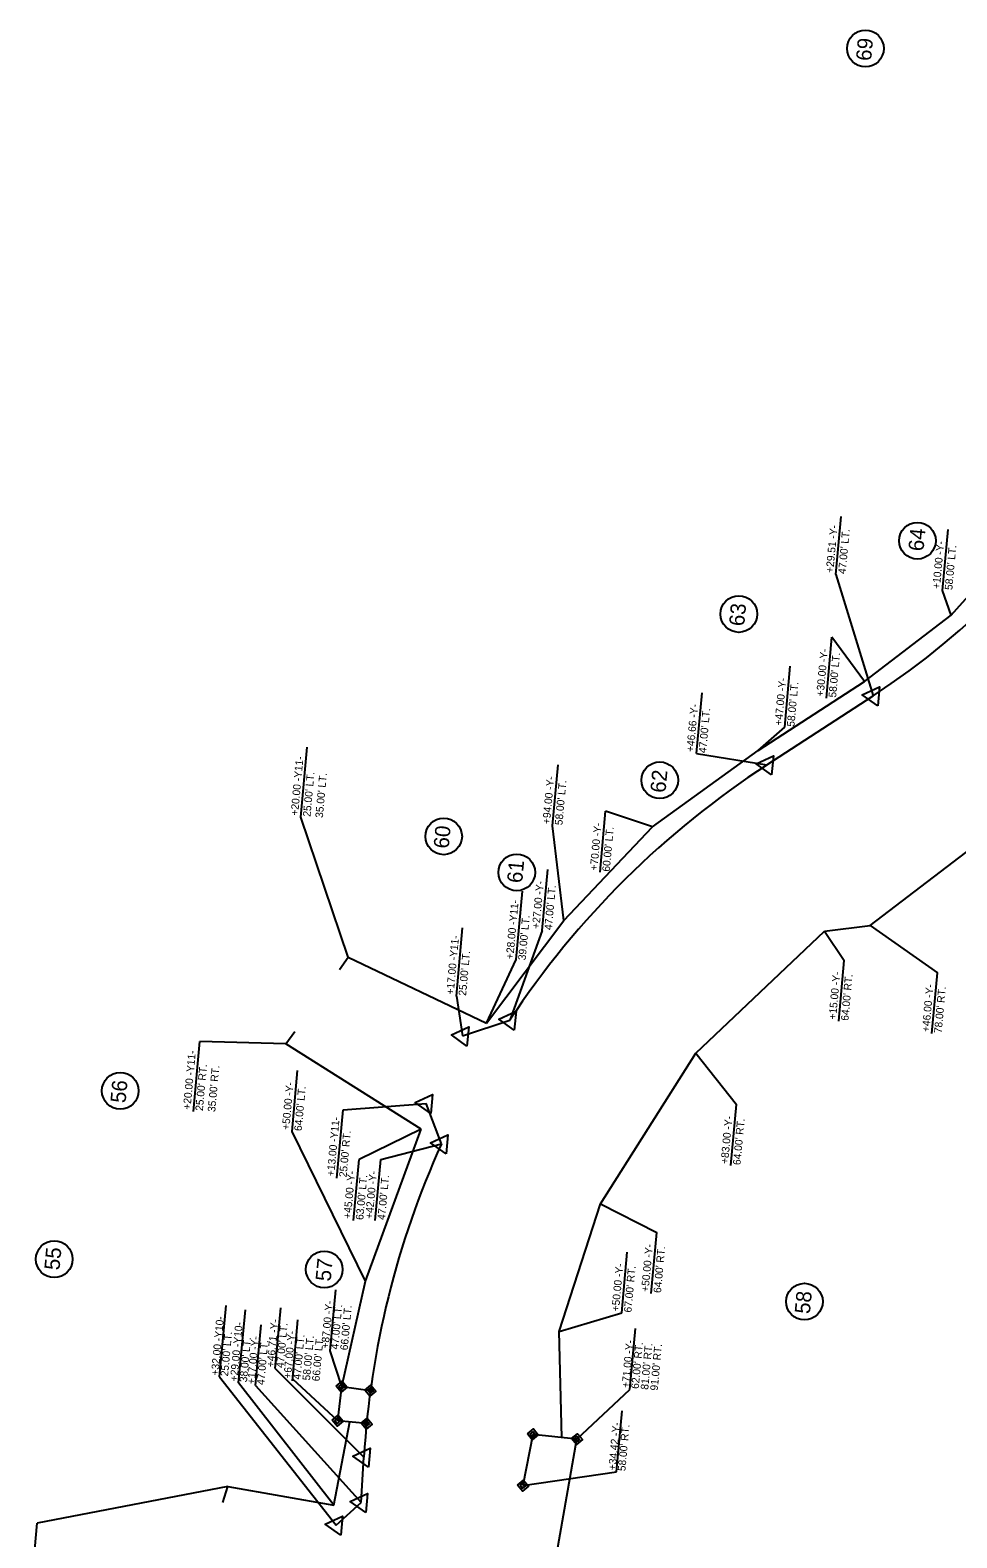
# Model space of a CAD drawing. Extents: x 2010883 to 2014849, y 442000 to 447413.
# Drawn here: x 2011804 to 2012411, y 445432 to 446419 of the extents above; entities that cross this region are included whole.
import ezdxf

# ---------------------------------------------------------------- set-up
doc = ezdxf.new("R2010")
doc.units = 0
for name, color, linetype in [('Prop Easement Construction', 7, 'Continuous'), ('Prop Easement Construction Station Offsets', 7, 'Continuous'), ('Prop Easement Permanent Drainage', 7, 'Continuous'), ('Prop Easement Permanent Utility', 7, 'Continuous'), ('Prop Easement Permanent Utility Station Offsets', 7, 'Continuous'), ('Prop Parcel Number CELL', 7, 'Continuous'), ('Prop Parcel Number Text', 7, 'Continuous'), ('Prop ROW Marker CELL', 7, 'Continuous'), ('Prop ROW Permanent Easement CELL', 7, 'Continuous'), ('Prop ROW RW Lines', 7, 'Continuous'), ('Prop ROW Station Offsets', 7, 'Continuous')]:
    doc.layers.add(name, color=color, linetype=linetype)

msp = doc.modelspace()

# ---------------------------------------------------------------- linework, layer by layer
at = {"layer": 'Prop Easement Construction'}
for p, q in [((2012407.17, 446035.72), (2012483.95, 446122.35)), ((2012350.43, 445992.48), (2012407.17, 446035.72)), ((2012280.87, 445947.29), (2012350.43, 445992.48)), ((2012211.57, 445897.38), (2012280.87, 445947.29)), ((2012153.67, 445836.06), (2012211.57, 445897.38)), ((2012354.2, 445832.75), (2012445.39, 445902.48)), ((2012102.87, 445768.83), (2012153.67, 445836.06)), ((2012240.02, 445749.18), (2012324.14, 445828.93)), ((2012324.14, 445828.93), (2012354.2, 445832.75)), ((2012006.62, 445803.98), (2012012.44, 445812.11)), ((2012012.44, 445812.11), (2012102.87, 445768.83)), ((2011971.66, 445755.22), (2011977.49, 445763.35)), ((2012060.29, 445699.56), (2011971.66, 445755.22)), ((2012177.54, 445650.51), (2012240.02, 445749.18)), ((2012023.75, 445599.9), (2012060.29, 445699.56)), ((2012150.57, 445567.08), (2012177.54, 445650.51)), ((2012008.16, 445531), (2012023.75, 445599.9)), ((2012152.18, 445497.67), (2012150.57, 445567.08)), ((2012002.92, 445453.48), (2012013.5, 445507.91)), ((2011930.27, 445455.17), (2011933.71, 445465.62)), ((2011933.71, 445465.62), (2012002.92, 445453.48))]:
    msp.add_line(p, q, dxfattribs=at)
at = {"layer": 'Prop Easement Construction Station Offsets'}
for p, q in [((2012401.51, 446051.91), (2012405.17, 446091.75)), ((2012407.17, 446035.72), (2012401.51, 446051.91)), ((2012325.42, 445981.55), (2012329.08, 446021.38)), ((2012350.43, 445992.48), (2012329.08, 446021.38)), ((2012298.15, 445962.5), (2012301.81, 446002.33)), ((2012280.87, 445947.29), (2012298.15, 445962.5)), ((2011981.37, 445903.57), (2011985.58, 445949.38)), ((2012146.25, 445898.02), (2012149.92, 445937.85)), ((2012177.27, 445867.64), (2012180.93, 445907.48)), ((2012211.57, 445897.38), (2012180.93, 445907.48)), ((2012012.44, 445812.11), (2011981.37, 445903.57)), ((2012153.67, 445836.06), (2012146.25, 445898.02)), ((2012122.31, 445810.4), (2012126.43, 445855.21)), ((2012324.14, 445828.93), (2012337.19, 445809.92)), ((2012354.2, 445832.75), (2012398.23, 445801.79)), ((2012102.87, 445768.83), (2012122.31, 445810.4)), ((2012333.53, 445770.09), (2012337.19, 445809.92)), ((2012394.57, 445761.96), (2012398.23, 445801.79)), ((2011911.07, 445710.93), (2011915.28, 445756.74)), ((2011971.66, 445755.22), (2011915.28, 445756.74)), ((2012240.02, 445749.18), (2012266.53, 445715.49)), ((2011975.63, 445697.91), (2011979.29, 445737.74)), ((2012262.86, 445675.66), (2012266.53, 445715.49)), ((2012023.75, 445599.9), (2011975.63, 445697.91)), ((2012060.29, 445699.56), (2012019.59, 445679.57)), ((2012015.93, 445639.74), (2012019.59, 445679.57)), ((2012177.54, 445650.51), (2012214.48, 445631.77)), ((2012210.82, 445591.94), (2012214.48, 445631.77)), ((2012191.48, 445579.18), (2012195.14, 445619.01)), ((2012000.57, 445554.51), (2012004.23, 445594.35)), ((2011940.7, 445533.45), (2011945.09, 445581.25)), ((2012150.57, 445567.08), (2012191.48, 445579.18)), ((2011975.89, 445534.77), (2011979.55, 445574.6)), ((2012008.16, 445531), (2012000.57, 445554.51)), ((2012002.92, 445453.48), (2011940.7, 445533.45)), ((2012005.54, 445508.69), (2011976.19, 445535.9)), ((2011933.71, 445465.62), (2011808.88, 445441.67)), ((2011804.21, 445390.84), (2011808.88, 445441.67))]:
    msp.add_line(p, q, dxfattribs=at)
at = {"layer": 'Prop Easement Permanent Drainage'}
for p, q in [((2012005.54, 445508.69), (2012008.16, 445531)), ((2012008.16, 445531), (2012026.98, 445528.44)), ((2012005.65, 445509.81), (2012005.65, 445509.81)), ((2012005.65, 445509.81), (2012005.65, 445509.81)), ((2012024.45, 445506.83), (2012005.54, 445508.69))]:
    msp.add_line(p, q, dxfattribs=at)
at = {"layer": 'Prop Easement Permanent Utility'}
for p, q in [((2012119.36, 445252.89), (2012162.12, 445496.62)), ((2012133.28, 445499.67), (2012126.77, 445466.24)), ((2012162.12, 445496.62), (2012133.28, 445499.67))]:
    msp.add_line(p, q, dxfattribs=at)
at = {"layer": 'Prop Easement Permanent Utility Station Offsets'}
for p, q in [((2012196.86, 445529.16), (2012200.52, 445568.99)), ((2012162.12, 445496.62), (2012196.86, 445529.16)), ((2012188.1, 445475.3), (2012191.76, 445515.13)), ((2012126.77, 445466.24), (2012188.1, 445475.3))]:
    msp.add_line(p, q, dxfattribs=at)
at = {"layer": 'Prop Parcel Number CELL'}
for p, q in [((2012351.01, 446406.59), (2012351.01, 446406.59)), ((2012385.03, 446084.49), (2012385.03, 446084.49)), ((2012268.15, 446036.54), (2012268.15, 446036.54)), ((2012216.35, 445927.76), (2012216.35, 445927.76)), ((2012074.93, 445891.05), (2012074.93, 445891.05)), ((2012122.77, 445867.45), (2012122.77, 445867.45)), ((2011863.21, 445724.55), (2011863.21, 445724.55)), ((2011819.99, 445614.37), (2011819.99, 445614.37)), ((2011996.75, 445607.67), (2011996.75, 445607.67)), ((2012311.04, 445586.6), (2012311.04, 445586.6))]:
    msp.add_line(p, q, dxfattribs=at)
for centre in [(2012351.01, 446406.59), (2012385.03, 446084.49), (2012268.15, 446036.54), (2012216.35, 445927.76), (2012074.93, 445891.05), (2012122.77, 445867.45), (2011863.21, 445724.55), (2011819.99, 445614.37), (2011996.75, 445607.67), (2012311.04, 445586.6)]:
    msp.add_circle(centre, 12, dxfattribs=at)
at = {"layer": 'Prop ROW Marker CELL'}
for p, q in [((2012356.05, 445983.01), (2012356.05, 445983.01)), ((2012286.57, 445937.88), (2012286.57, 445937.88)), ((2012118.13, 445770.76), (2012118.13, 445770.76)), ((2012087.17, 445760.42), (2012087.17, 445760.42)), ((2012063.42, 445716.24), (2012063.42, 445716.24)), ((2012073.47, 445689.9), (2012073.47, 445689.9)), ((2012008.16, 445531), (2012008.16, 445531)), ((2012026.98, 445528.44), (2012026.98, 445528.44)), ((2012005.54, 445508.69), (2012005.54, 445508.69)), ((2012024.45, 445506.83), (2012024.45, 445506.83)), ((2012133.28, 445499.67), (2012133.28, 445499.67)), ((2012162.12, 445496.62), (2012162.12, 445496.62)), ((2012022.7, 445484.83), (2012022.7, 445484.83)), ((2012126.77, 445466.24), (2012126.77, 445466.24)), ((2012020.92, 445455.17), (2012020.92, 445455.17)), ((2012004.58, 445440.31), (2012004.58, 445440.31))]:
    msp.add_line(p, q, dxfattribs=at)
for points in [[(2012359.06, 445976.46), (2012348.88, 445983.67), (2012360.21, 445988.91)], [(2012289.59, 445931.32), (2012279.4, 445938.54), (2012290.73, 445943.77)], [(2012121.14, 445764.21), (2012110.96, 445771.42), (2012122.29, 445776.66)], [(2012090.18, 445753.87), (2012080, 445761.08), (2012091.33, 445766.32)], [(2012066.43, 445709.69), (2012056.25, 445716.9), (2012067.58, 445722.14)], [(2012076.48, 445683.35), (2012066.3, 445690.56), (2012077.63, 445695.8)], [(2012025.71, 445478.27), (2012015.53, 445485.49), (2012026.86, 445490.72)], [(2012023.93, 445448.62), (2012013.75, 445455.83), (2012025.07, 445461.06)], [(2012007.59, 445433.75), (2011997.41, 445440.97), (2012008.74, 445446.2)]]:
    msp.add_lwpolyline(points, close=True, dxfattribs=at)
at = {"layer": 'Prop ROW Permanent Easement CELL'}
for points in [[(2012004.57, 445531.33), (2012008.49, 445534.59), (2012011.74, 445530.67), (2012007.83, 445527.42)], [(2012006.36, 445531.17), (2012008.32, 445532.8), (2012009.95, 445530.84), (2012007.99, 445529.21)], [(2012023.4, 445528.77), (2012027.31, 445532.02), (2012030.57, 445528.11), (2012026.65, 445524.85)], [(2012025.19, 445528.6), (2012027.15, 445530.23), (2012028.77, 445528.27), (2012026.82, 445526.64)], [(2012001.95, 445509.02), (2012005.87, 445512.27), (2012009.12, 445508.36), (2012005.21, 445505.1)], [(2012003.75, 445508.85), (2012005.7, 445510.48), (2012007.33, 445508.52), (2012005.37, 445506.9)], [(2012020.86, 445507.16), (2012024.78, 445510.41), (2012028.03, 445506.5), (2012024.12, 445503.24)], [(2012022.65, 445506.99), (2012024.61, 445508.62), (2012026.24, 445506.66), (2012024.28, 445505.04)], [(2012129.7, 445500), (2012133.61, 445503.26), (2012136.87, 445499.34), (2012132.95, 445496.09)], [(2012131.49, 445499.84), (2012133.45, 445501.46), (2012135.07, 445499.51), (2012133.12, 445497.88)], [(2012158.54, 445496.95), (2012162.45, 445500.2), (2012165.7, 445496.29), (2012161.79, 445493.03)], [(2012160.33, 445496.78), (2012162.29, 445498.41), (2012163.91, 445496.45), (2012161.96, 445494.82)], [(2012123.19, 445466.57), (2012127.1, 445469.83), (2012130.36, 445465.91), (2012126.44, 445462.66)], [(2012124.98, 445466.41), (2012126.94, 445468.04), (2012128.56, 445466.08), (2012126.61, 445464.45)]]:
    msp.add_lwpolyline(points, close=True, dxfattribs=at)
at = {"layer": 'Prop ROW RW Lines'}
for p, q in [((2012286.57, 445937.88), (2012356.05, 445983.01)), ((2012087.17, 445760.42), (2012118.13, 445770.76)), ((2012073.47, 445689.9), (2012063.42, 445716.24)), ((2012020.92, 445455.17), (2012022.7, 445484.82)), ((2012004.58, 445440.31), (2012020.92, 445455.17))]:
    msp.add_line(p, q, dxfattribs=at)
for centre, radius, start, end in [((2012087.46, 446396.43), 493, 303.01114, 355.42659), ((2012603.65, 445449.83), 582, 123.01114, 146.53516), ((2012603.65, 445449.83), 582, 155.63823, 176.55328)]:
    msp.add_arc(centre, radius, start, end, dxfattribs=at)
at = {"layer": 'Prop ROW Station Offsets'}
for p, q in [((2012331.7, 446062.42), (2012335.18, 446100.26)), ((2012331.7, 446062.42), (2012356.05, 445983.01)), ((2012240.4, 445945.21), (2012244.06, 445985.04)), ((2012240.4, 445945.21), (2012286.57, 445937.88)), ((2012139.37, 445829.44), (2012143.04, 445869.27)), ((2012083.22, 445786.43), (2012087.34, 445831.24)), ((2012139.37, 445829.44), (2012118.13, 445770.76)), ((2012083.22, 445786.43), (2012087.17, 445760.42)), ((2012005.01, 445667.32), (2012009.13, 445712.13)), ((2012009.13, 445712.13), (2012063.42, 445716.24)), ((2012033.85, 445679.55), (2012073.47, 445689.9)), ((2012030.18, 445639.72), (2012033.85, 445679.55)), ((2011928.19, 445537.31), (2011932.49, 445584.11)), ((2011964.62, 445542.81), (2011968.28, 445582.64)), ((2011951.83, 445531.67), (2011955.49, 445571.5)), ((2011964.62, 445542.81), (2012022.7, 445484.82)), ((2011928.19, 445537.31), (2012004.58, 445440.31)), ((2011951.83, 445531.67), (2012020.92, 445455.17))]:
    msp.add_line(p, q, dxfattribs=at)

# ---------------------------------------------------------------- texts
at = {"layer": 'Prop Easement Construction Station Offsets'}
for s, p in [('+10.00 -Y-', (2012399.75, 446052.8)), ("58.00' LT.", (2012407.84, 446052.06)), ('+30.00 -Y-', (2012323.66, 445982.44)), ("58.00' LT.", (2012331.76, 445981.7)), ('+47.00 -Y-', (2012296.39, 445963.39)), ("58.00' LT.", (2012304.48, 445962.64)), ('+20.00 -Y11-', (2011979.61, 445904.46)), ("25.00' LT.", (2011987.7, 445903.72)), ("35.00' LT.", (2011995.8, 445902.97)), ('+94.00 -Y-', (2012144.5, 445898.91)), ("58.00' LT.", (2012152.59, 445898.17)), ('+70.00 -Y-', (2012175.51, 445868.53)), ("60.00' LT.", (2012183.6, 445867.79)), ('+28.00 -Y11-', (2012120.48, 445810.54)), ("39.00' LT.", (2012128.57, 445809.8)), ('+15.00 -Y-', (2012331.77, 445770.98)), ("64.00' RT.", (2012339.86, 445770.23)), ('+46.00 -Y-', (2012392.81, 445762.85)), ("78.00' RT.", (2012400.9, 445762.11)), ('+20.00 -Y11-', (2011909.16, 445712.01)), ("25.00' RT.", (2011917.25, 445711.27)), ("35.00' RT.", (2011925.34, 445710.52)), ('+50.00 -Y-', (2011973.87, 445698.8)), ("64.00' LT.", (2011981.96, 445698.05)), ('+83.00 -Y-', (2012261.11, 445676.55)), ("64.00' RT.", (2012269.2, 445675.81)), ('+45.00 -Y-', (2012014.17, 445640.63)), ("63.00' LT.", (2012022.26, 445639.89)), ('+50.00 -Y-', (2012209.07, 445592.83)), ("64.00' RT.", (2012217.16, 445592.09)), ('+50.00 -Y-', (2012189.72, 445580.06)), ("67.00' RT.", (2012197.81, 445579.32)), ('+87.00 -Y-', (2011999.62, 445555.76)), ("47.00' LT.", (2012005.85, 445555.18)), ("66.00' LT.", (2012012.07, 445554.61)), ('+29.00 -Y10-', (2011939.91, 445534.25)), ("38.00' LT.", (2011946.13, 445533.68)), ('+67.00 -Y-', (2011974.94, 445536.01)), ("47.00' LT.", (2011981.17, 445535.44)), ("58.00' LT.", (2011987.39, 445534.87)), ("66.00' LT.", (2011993.61, 445534.3))]:
    msp.add_text(s, height=5, rotation=84.74666, dxfattribs=at).set_placement(p)
at = {"layer": 'Prop Easement Permanent Utility Station Offsets'}
for s, p in [('+71.00 -Y-', (2012196.35, 445529.94)), ("62.00' RT.", (2012202.58, 445529.36)), ("81.00' RT.", (2012208.8, 445528.79)), ("91.00' RT.", (2012215.03, 445528.22)), ('+34.42 -Y-', (2012187.6, 445476.08)), ("58.00' RT.", (2012193.82, 445475.5))]:
    msp.add_text(s, height=5, rotation=84.74666, dxfattribs=at).set_placement(p)
at = {"layer": 'Prop Parcel Number Text'}
for s, p in [('69', (2012354.7, 446398.18)), ('64', (2012388.98, 446077.36)), ('63', (2012271.6, 446028.31)), ('62', (2012220.09, 445919.29)), ('60', (2012078.21, 445882.8)), ('61', (2012126.27, 445860.2)), ('56', (2011866.65, 445716.27)), ('55', (2011823.39, 445606.9)), ('57', (2012000.95, 445599.6)), ('58', (2012314.6, 445578.29))]:
    msp.add_text(s, height=10, rotation=84.74666, dxfattribs=at).set_placement(p)
at = {"layer": 'Prop ROW Station Offsets'}
for s, p in [('+29.51 -Y-', (2012329.95, 446063.3)), ("47.00' LT.", (2012338.04, 446062.56)), ('+46.66 -Y-', (2012238.64, 445946.1)), ("47.00' LT.", (2012246.73, 445945.36)), ('+27.00 -Y-', (2012137.62, 445830.33)), ("47.00' LT.", (2012145.71, 445829.58)), ('+17.00 -Y11-', (2012081.46, 445787.31)), ("25.00' LT.", (2012089.55, 445786.57)), ('+13.00 -Y11-', (2012003.29, 445668.55)), ("25.00' RT.", (2012011.38, 445667.81)), ('+42.00 -Y-', (2012028.43, 445640.61)), ("47.00' LT.", (2012036.52, 445639.87)), ('+32.00 -Y10-', (2011927.51, 445538.1)), ('+46.71 -Y-', (2011963.89, 445543.6)), ("47.00' LT.", (2011970.11, 445543.03)), ("25.00' LT.", (2011933.74, 445537.52)), ('+17.00 -Y-', (2011951.19, 445532.46)), ("47.00' LT.", (2011957.42, 445531.89))]:
    msp.add_text(s, height=5, rotation=84.74666, dxfattribs=at).set_placement(p)

doc.saveas('drawing.dxf')
